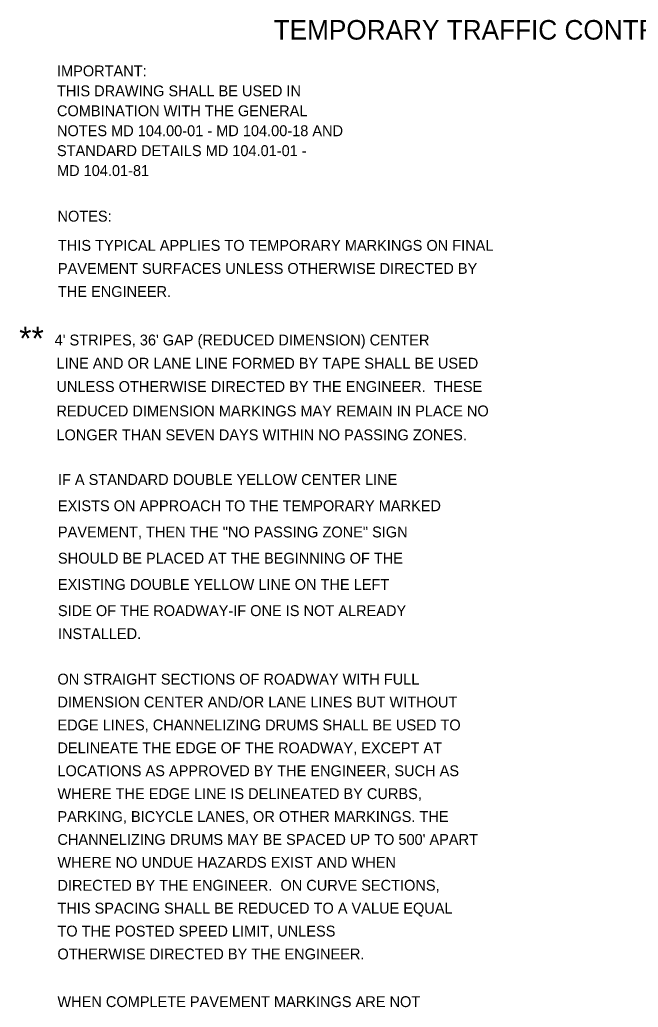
# Model space of a CAD drawing. Extents: x 612.5 to 619.9, y 611 to 621.2.
# Drawn here: x 612.74 to 616.15, y 615.75 to 621.2 of the extents above; entities that cross this region are included whole.
import ezdxf

# ---------------------------------------------------------------- set-up
doc = ezdxf.new("R2010")
doc.units = 0
doc.layers.add('DETL-NOTE', color=7, linetype='Continuous')
doc.layers.add('DETL-TITL', color=7, linetype='Continuous')

msp = doc.modelspace()

# ---------------------------------------------------------------- texts
at = {"layer": 'DETL-NOTE'}
for s, height, p in [('IMPORTANT:', 0.06, (612.9421, 620.883)), ('THIS DRAWING SHALL BE USED IN', 0.06, (612.9421, 620.773)), ('COMBINATION WITH THE GENERAL', 0.06, (612.9421, 620.663)), ('NOTES MD 104.00-01 - MD 104.00-18 AND', 0.06, (612.9421, 620.553)), ('STANDARD DETAILS MD 104.01-01 -', 0.06, (612.9421, 620.443)), ('MD 104.01-81', 0.06, (612.9421, 620.333)), ('NOTES:', 0.06, (612.945, 620.0815)), ('THIS TYPICAL APPLIES TO TEMPORARY MARKINGS ON FINAL', 0.06, (612.9474, 619.9202)), ('PAVEMENT SURFACES UNLESS OTHERWISE DIRECTED BY ', 0.06, (612.9474, 619.7929)), ('THE ENGINEER.', 0.06, (612.9474, 619.6656)), ('**', 0.13026, (612.7339, 619.3719)), ("4' STRIPES, 36' GAP (REDUCED DIMENSION) CENTER", 0.06, (612.9292, 619.398)), ('LINE AND OR LANE LINE FORMED BY TAPE SHALL BE USED', 0.06, (612.9391, 619.2699)), ('UNLESS OTHERWISE DIRECTED BY THE ENGINEER.  THESE', 0.06, (612.9391, 619.1413)), ('REDUCED DIMENSION MARKINGS MAY REMAIN IN PLACE NO', 0.06, (612.9391, 619.0066)), ('LONGER THAN SEVEN DAYS WITHIN NO PASSING ZONES.', 0.06, (612.9391, 618.8746)), ('IF A STANDARD DOUBLE YELLOW CENTER LINE', 0.06, (612.9474, 618.628)), ('EXISTS ON APPROACH TO THE TEMPORARY MARKED', 0.06, (612.9474, 618.4834)), ('PAVEMENT, THEN THE "NO PASSING ZONE" SIGN', 0.06, (612.9474, 618.3386)), ('SHOULD BE PLACED AT THE BEGINNING OF THE', 0.06, (612.9474, 618.1938)), ('EXISTING DOUBLE YELLOW LINE ON THE LEFT', 0.06, (612.9474, 618.0492)), ('SIDE OF THE ROADWAY-IF ONE IS NOT ALREADY', 0.06, (612.9474, 617.9044)), ('INSTALLED.', 0.06, (612.9474, 617.7772)), ('ON STRAIGHT SECTIONS OF ROADWAY WITH FULL', 0.06, (612.9446, 617.5265)), ('DIMENSION CENTER AND/OR LANE LINES BUT WITHOUT', 0.06, (612.9446, 617.4001)), ('EDGE LINES, CHANNELIZING DRUMS SHALL BE USED TO', 0.06, (612.9446, 617.2737)), ('DELINEATE THE EDGE OF THE ROADWAY, EXCEPT AT', 0.06, (612.9446, 617.1473)), ('LOCATIONS AS APPROVED BY THE ENGINEER, SUCH AS', 0.06, (612.9446, 617.0209)), ('WHERE THE EDGE LINE IS DELINEATED BY CURBS,', 0.06, (612.9446, 616.8945)), ('PARKING, BICYCLE LANES, OR OTHER MARKINGS. THE ', 0.06, (612.9446, 616.7681)), ("CHANNELIZING DRUMS MAY BE SPACED UP TO 500' APART", 0.06, (612.9446, 616.6417)), ('WHERE NO UNDUE HAZARDS EXIST AND WHEN', 0.06, (612.9446, 616.5153)), ('DIRECTED BY THE ENGINEER.  ON CURVE SECTIONS,', 0.06, (612.9446, 616.3889)), ('THIS SPACING SHALL BE REDUCED TO A VALUE EQUAL', 0.06, (612.9446, 616.2625)), ('TO THE POSTED SPEED LIMIT, UNLESS', 0.06, (612.9446, 616.1361)), ('OTHERWISE DIRECTED BY THE ENGINEER.', 0.06, (612.9446, 616.0097)), ('WHEN COMPLETE PAVEMENT MARKINGS ARE NOT', 0.06, (612.9446, 615.7466))]:
    msp.add_text(s, height=height, dxfattribs=at).set_placement(p)
at = {"layer": 'DETL-TITL'}
msp.add_text('TEMPORARY TRAFFIC CONTROL TYPICAL APPLICATION', height=0.108, dxfattribs=at).set_placement((614.1375, 621.0859))

doc.saveas('drawing.dxf')
